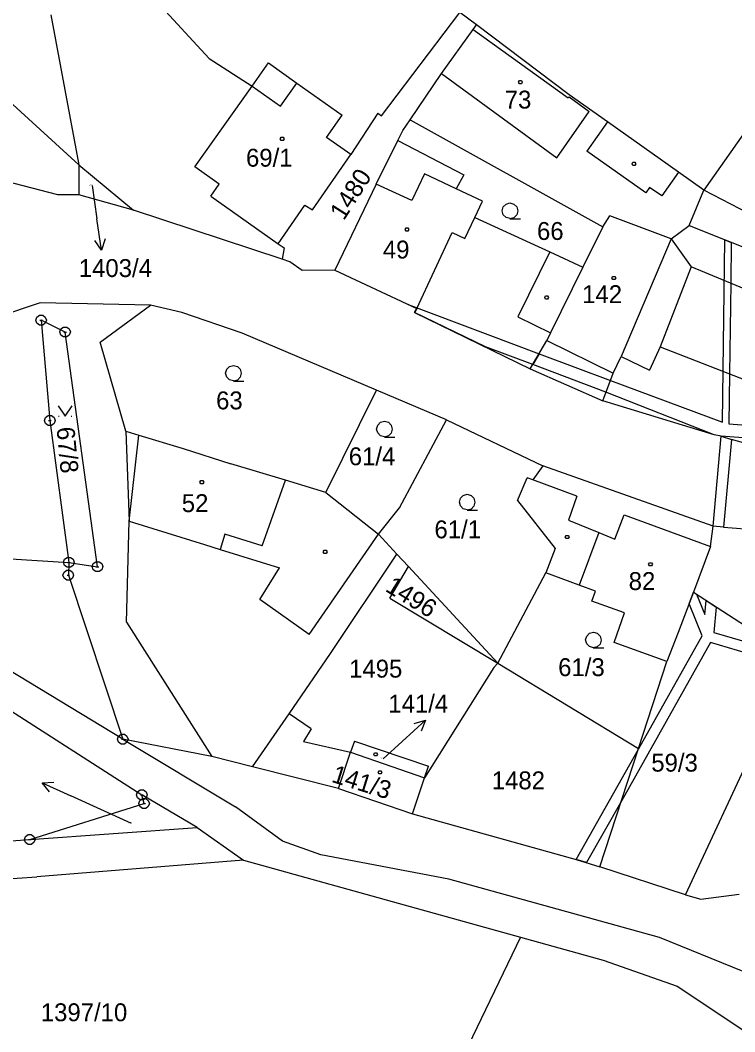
# Model space of a CAD drawing. Extents: x -850689 to -847910, y -1058374 to -1054747.
# Drawn here: x -849235.3 to -849167.4, y -1056250.1 to -1056154 of the extents above; entities that cross this region are included whole.
import ezdxf

# ---------------------------------------------------------------- set-up
doc = ezdxf.new("R2010")
doc.units = 0
for name, color, linetype in [('KN_BREMENA', 7, 'Continuous'), ('KN_HRANICE', 7, 'Continuous'), ('KN_KULTURY', 7, 'Continuous'), ('KN_MEZNIKY', 7, 'Continuous'), ('KN_PARCELY', 7, 'Continuous'), ('KN_SLUCKY', 7, 'Continuous'), ('KN_STAVEBNI', 7, 'Continuous')]:
    doc.layers.add(name, color=color, linetype=linetype)

# ---------------------------------------------------------------- blocks, each defined once
blk = doc.blocks.new('304')
blk.add_lwpolyline([(0, 0), (-0.38, 0.1), (-0.65, 0.37), (-0.75, 0.74), (-0.65, 1.11), (-0.38, 1.38), (-0.01, 1.48), (0.36, 1.38), (0.63, 1.11), (0.73, 0.73), (0.63, 0.35), (0.36, 0.08), (-0.02, -0.02), (0.98, -0.02)])
blk = doc.blocks.new('314')
for p, q in [((-0.95, 0), (-0.85, 0)), ((0.85, 0), (0.95, 0))]:
    blk.add_line(p, q)
blk.add_lwpolyline([(-1, 1.5), (0, 0), (1, 1.5)])
blk = doc.blocks.new('10292')
blk.add_line((0, 3), (0, 0))
blk.add_lwpolyline([(-0.5, 2), (0, 3), (0.5, 2)])
blk = doc.blocks.new('402')
blk.add_lwpolyline([(0.09, 0.15), (0.18, 0), (0.09, -0.15), (-0.09, -0.15), (-0.18, 0), (-0.09, 0.15), (0.09, 0.15)])
blk = doc.blocks.new('105')
blk.add_line((-0.12, 0), (0.12, 0))
blk.add_lwpolyline([(0.15, 0.48), (0.4, 0.3), (0.5, 0.01), (0.4, -0.28), (0.15, -0.46), (-0.16, -0.46), (-0.41, -0.28), (-0.51, 0.01), (-0.41, 0.3), (-0.16, 0.48), (0.15, 0.48)])

msp = doc.modelspace()

# ---------------------------------------------------------------- linework, layer by layer
at = {"layer": 'KN_BREMENA'}
for p, q in [((-849168.3, -1056174.91), (-849167.7, -1056175.15)), ((-849182.44, -1056233.76), (-849176.53, -1056223.29))]:
    msp.add_line(p, q, dxfattribs=at)
for points in [[(-849179.61, -1056189.36), (-849186.57, -1056186.75), (-849185.97, -1056185.74), (-849179.19, -1056188.26), (-849168.53, -1056192.22), (-849168.3, -1056174.91)], [(-849167.7, -1056175.15), (-849167.75, -1056179.02), (-849167.87, -1056187.62), (-849167.93, -1056192.39)], [(-849167.93, -1056192.39), (-849153, -1056193.52), (-849137.98, -1056194.65), (-849138.63, -1056195.81), (-849147.02, -1056195.18), (-849168.67, -1056193.56), (-849169.32, -1056193.41), (-849179.61, -1056189.36)], [(-849176.53, -1056223.29), (-849170.45, -1056212.52), (-849171.68, -1056209.54), (-849171.71, -1056209.46), (-849171.3, -1056208.37), (-849171, -1056208.57), (-849170.2, -1056210.49), (-849170.09, -1056209.16), (-849169.12, -1056209.78), (-849169.34, -1056212.19)], [(-849169.34, -1056212.19), (-849162.17, -1056214.28), (-849161.61, -1056214.65), (-849161.96, -1056215.41), (-849169.66, -1056213.16), (-849178.11, -1056228.14), (-849181.45, -1056234.05), (-849182.44, -1056233.76)]]:
    msp.add_lwpolyline(points, dxfattribs=at)
for points in [[(-849186.57, -1056186.75), (-849191.06, -1056185.07), (-849197.79, -1056181.8), (-849197.58, -1056181.42), (-849198.41, -1056181.03), (-849185.97, -1056185.74)], [(-849168.67, -1056193.56), (-849167.69, -1056193.85), (-849168.44, -1056202.2), (-849169.42, -1056202.11)]]:
    msp.add_lwpolyline(points, close=True, dxfattribs=at)
at = {"layer": 'KN_HRANICE'}
for p, q in [((-849253.4, -1056146.22), (-849229.69, -1056167.78)), ((-849222.61, -1056151.92), (-849217.32, -1056157.67)), ((-849232.38, -1056153.52), (-849229.69, -1056167.78)), ((-849200.94, -1056163.12), (-849193.48, -1056153.3)), ((-849191.92, -1056154.48), (-849193.48, -1056153.3)), ((-849192.23, -1056154.91), (-849191.92, -1056154.48)), ((-849183.09, -1056161.13), (-849191.92, -1056154.48)), ((-849195.24, -1056159.11), (-849192.23, -1056154.91)), ((-849217.32, -1056157.67), (-849213.24, -1056160.29)), ((-849213.24, -1056160.29), (-849211.69, -1056158.1)), ((-849211.69, -1056158.1), (-849209, -1056160.01)), ((-849198.23, -1056163.51), (-849195.24, -1056159.11)), ((-849218.67, -1056167.97), (-849213.24, -1056160.29)), ((-849209, -1056160.01), (-849204.67, -1056163.07)), ((-849179.47, -1056163.69), (-849183.09, -1056161.13)), ((-849163.93, -1056161.11), (-849170.31, -1056170.18)), ((-849206.17, -1056165.19), (-849204.67, -1056163.07)), ((-849201.3, -1056162.87), (-849203.87, -1056166.8)), ((-849201.3, -1056162.87), (-849200.94, -1056163.12)), ((-849198.91, -1056164.5), (-849198.23, -1056163.51)), ((-849198.23, -1056163.51), (-849179.92, -1056173.67)), ((-849172.72, -1056168.47), (-849179.47, -1056163.69)), ((-849199.39, -1056165.45), (-849198.91, -1056164.5)), ((-849203.87, -1056166.8), (-849206.17, -1056165.19)), ((-849201.46, -1056169.6), (-849199.39, -1056165.45)), ((-849199.39, -1056165.45), (-849193.13, -1056168.74)), ((-849207.51, -1056172.06), (-849203.87, -1056166.8)), ((-849229.69, -1056167.78), (-849229.7, -1056170.62)), ((-849229.69, -1056167.78), (-849224.5, -1056172.08)), ((-849216.36, -1056169.6), (-849218.67, -1056167.97)), ((-849231.7, -1056170.64), (-849240.7, -1056168.28)), ((-849193.13, -1056168.74), (-849193.84, -1056170.06)), ((-849170.31, -1056170.18), (-849172.72, -1056168.47)), ((-849217.17, -1056170.75), (-849216.36, -1056169.6)), ((-849201.46, -1056169.6), (-849205.39, -1056177.77)), ((-849229.7, -1056170.62), (-849231.7, -1056170.64)), ((-849224.5, -1056172.08), (-849229.7, -1056170.62)), ((-849217.17, -1056170.75), (-849210.75, -1056175.28)), ((-849191.35, -1056171.24), (-849193.84, -1056170.06)), ((-849171.71, -1056173.55), (-849170.31, -1056170.18)), ((-849157.98, -1056176.57), (-849170.31, -1056170.18)), ((-849210.75, -1056175.28), (-849208.24, -1056171.61)), ((-849208.24, -1056171.61), (-849207.51, -1056172.06)), ((-849192.07, -1056172.77), (-849191.35, -1056171.24)), ((-849210.39, -1056176.75), (-849224.5, -1056172.08)), ((-849192.07, -1056172.77), (-849184.95, -1056176.04)), ((-849179.92, -1056173.67), (-849179.25, -1056172.62)), ((-849173.41, -1056174.79), (-849179.25, -1056172.62)), ((-849179.92, -1056173.67), (-849181.8, -1056177.49)), ((-849173.41, -1056174.79), (-849171.71, -1056173.55)), ((-849171.71, -1056173.55), (-849158.94, -1056178.64)), ((-849210.75, -1056175.28), (-849210.2, -1056175.67)), ((-849210.2, -1056175.67), (-849210.39, -1056176.75)), ((-849173.41, -1056174.79), (-849171.52, -1056177.46)), ((-849184.95, -1056176.04), (-849181.8, -1056177.49)), ((-849209.65, -1056177), (-849210.39, -1056176.75)), ((-849208.48, -1056177.82), (-849209.65, -1056177)), ((-849181.8, -1056177.49), (-849184.87, -1056183.74)), ((-849171.52, -1056177.46), (-849174.47, -1056185.05)), ((-849205.39, -1056177.77), (-849208.48, -1056177.82)), ((-849205.39, -1056177.77), (-849197.58, -1056181.42)), ((-849233.39, -1056180.87), (-849242.54, -1056183.94)), ((-849222.9, -1056181.1), (-849233.39, -1056180.87)), ((-849227.69, -1056184.62), (-849222.9, -1056181.1)), ((-849219.9, -1056181.81), (-849222.9, -1056181.1)), ((-849197.58, -1056181.42), (-849197.79, -1056181.8)), ((-849214.19, -1056183.77), (-849219.9, -1056181.81)), ((-849197.79, -1056181.8), (-849186.8, -1056187.14)), ((-849231.01, -1056183.66), (-849233.29, -1056182.54)), ((-849233.29, -1056182.54), (-849232.46, -1056192.07)), ((-849227.93, -1056205.95), (-849231.01, -1056183.66)), ((-849201.43, -1056189.17), (-849214.19, -1056183.77)), ((-849184.87, -1056183.74), (-849185.22, -1056184.46)), ((-849225.23, -1056193.06), (-849227.69, -1056184.62)), ((-849186.8, -1056187.14), (-849185.22, -1056184.46)), ((-849174.47, -1056185.05), (-849175.47, -1056187.27)), ((-849178.93, -1056187.55), (-849178.15, -1056185.97)), ((-849178.15, -1056185.97), (-849175.47, -1056187.27)), ((-849186.8, -1056187.14), (-849179.92, -1056190.19)), ((-849179.92, -1056190.19), (-849178.93, -1056187.55)), ((-849206.24, -1056198.9), (-849201.43, -1056189.17)), ((-849194.76, -1056191.99), (-849201.43, -1056189.17)), ((-849169.32, -1056193.41), (-849179.92, -1056190.19)), ((-849199.24, -1056200.34), (-849194.76, -1056191.99)), ((-849194.76, -1056191.99), (-849185.6, -1056196.38)), ((-849232.46, -1056192.07), (-849230.65, -1056205.54)), ((-849225.23, -1056193.06), (-849224.93, -1056201.61)), ((-849225.23, -1056193.06), (-849223.99, -1056193.45)), ((-849223.99, -1056193.45), (-849219.79, -1056194.73)), ((-849168.67, -1056193.56), (-849169.32, -1056193.41)), ((-849168.67, -1056193.56), (-849167.69, -1056193.85)), ((-849164.4, -1056194.78), (-849167.69, -1056193.85)), ((-849219.79, -1056194.73), (-849215.25, -1056196.17)), ((-849210.06, -1056197.72), (-849215.25, -1056196.17)), ((-849185.6, -1056196.38), (-849186.57, -1056197.69)), ((-849169.42, -1056202.11), (-849185.6, -1056196.38)), ((-849206.24, -1056198.9), (-849210.06, -1056197.72)), ((-849188.02, -1056199.66), (-849187.1, -1056197.5)), ((-849186.57, -1056197.69), (-849187.1, -1056197.5)), ((-849206.24, -1056198.9), (-849201.22, -1056202.84)), ((-849188.02, -1056199.66), (-849184.45, -1056204.23)), ((-849201.22, -1056202.84), (-849199.24, -1056200.34)), ((-849225.19, -1056211.22), (-849224.93, -1056201.61)), ((-849225.53, -1056222.34), (-849258.09, -1056202.55)), ((-849169.66, -1056204.02), (-849169.42, -1056202.11)), ((-849168.44, -1056202.2), (-849169.42, -1056202.11)), ((-849168.44, -1056202.2), (-849162.53, -1056202.65)), ((-849201.22, -1056202.84), (-849199.47, -1056204.74)), ((-849184.45, -1056204.23), (-849185.31, -1056206.53)), ((-849169.66, -1056204.02), (-849171.3, -1056208.37)), ((-849259.01, -1056204.96), (-849223.72, -1056227.62)), ((-849236.17, -1056205.21), (-849230.65, -1056205.54)), ((-849205.78, -1056214.2), (-849199.47, -1056204.74)), ((-849199.47, -1056204.74), (-849198.37, -1056205.93)), ((-849230.65, -1056205.54), (-849230.7, -1056206.76)), ((-849230.65, -1056205.54), (-849227.93, -1056205.95)), ((-849200.16, -1056208.92), (-849198.37, -1056205.93)), ((-849198.37, -1056205.93), (-849189.89, -1056215.12)), ((-849230.7, -1056206.76), (-849225.53, -1056222.34)), ((-849189.89, -1056215.12), (-849185.31, -1056206.53)), ((-849182.16, -1056207.7), (-849185.31, -1056206.53)), ((-849180.61, -1056208.28), (-849182.16, -1056207.7)), ((-849180.96, -1056209.23), (-849180.61, -1056208.28)), ((-849171.3, -1056208.37), (-849172.75, -1056212.2)), ((-849171.3, -1056208.37), (-849161.61, -1056214.65)), ((-849200.16, -1056208.92), (-849189.89, -1056215.12)), ((-849177.84, -1056210.33), (-849180.96, -1056209.23)), ((-849225.19, -1056211.22), (-849217.08, -1056223.98)), ((-849178.84, -1056213.13), (-849177.84, -1056210.33)), ((-849172.75, -1056212.2), (-849173.81, -1056214.95)), ((-849173.81, -1056214.95), (-849178.84, -1056213.13)), ((-849209.73, -1056219.93), (-849205.78, -1056214.2)), ((-849189.89, -1056215.12), (-849190.25, -1056215.51)), ((-849189.89, -1056215.12), (-849176.5, -1056223.2)), ((-849176.5, -1056223.2), (-849173.81, -1056214.95)), ((-849172.06, -1056237.11), (-849161.61, -1056214.65)), ((-849190.25, -1056215.51), (-849196.84, -1056226)), ((-849213.19, -1056224.95), (-849209.73, -1056219.93)), ((-849207.63, -1056221.36), (-849209.73, -1056219.93)), ((-849207.63, -1056221.36), (-849208.34, -1056222.56)), ((-849217.08, -1056223.98), (-849225.53, -1056222.34)), ((-849225.53, -1056222.34), (-849214.82, -1056228.77)), ((-849208.34, -1056222.56), (-849203.88, -1056223.57)), ((-849203.52, -1056222.51), (-849203.88, -1056223.57)), ((-849203.52, -1056222.51), (-849196.47, -1056224.89)), ((-849203.88, -1056223.57), (-849196.84, -1056226)), ((-849180.18, -1056234.46), (-849176.5, -1056223.2)), ((-849213.19, -1056224.95), (-849217.08, -1056223.98)), ((-849205.03, -1056227), (-849213.19, -1056224.95)), ((-849196.84, -1056226), (-849196.47, -1056224.89)), ((-849197.99, -1056229.41), (-849196.84, -1056226)), ((-849205.03, -1056227), (-849197.99, -1056229.41)), ((-849234.37, -1056231.86), (-849223.5, -1056228.45)), ((-849218.47, -1056230.72), (-849223.72, -1056227.62)), ((-849223.5, -1056228.45), (-849223.72, -1056227.62)), ((-849210.34, -1056232), (-849214.82, -1056228.77)), ((-849197.99, -1056229.41), (-849182.44, -1056233.76)), ((-849234.37, -1056231.86), (-849218.47, -1056230.72)), ((-849218.47, -1056230.72), (-849214.07, -1056233.83)), ((-849244.07, -1056232.54), (-849234.37, -1056231.86)), ((-849206.7, -1056233.3), (-849210.34, -1056232)), ((-849194.53, -1056235.61), (-849206.7, -1056233.3)), ((-849214.07, -1056233.83), (-849233.7, -1056235.39)), ((-849214.07, -1056233.83), (-849187.73, -1056241.12)), ((-849182.44, -1056233.76), (-849180.18, -1056234.46)), ((-849172.06, -1056237.11), (-849180.18, -1056234.46)), ((-849273.28, -1056238.25), (-849233.7, -1056235.39)), ((-849174.51, -1056241.18), (-849194.53, -1056235.61)), ((-849172.06, -1056237.11), (-849170.59, -1056237.53)), ((-849170.59, -1056237.53), (-849166.94, -1056237.05)), ((-849187.73, -1056241.12), (-849195.81, -1056257.87)), ((-849187.73, -1056241.12), (-849179.87, -1056243.33)), ((-849166.56, -1056244.39), (-849174.51, -1056241.18)), ((-849179.87, -1056243.33), (-849172.85, -1056245.8)), ((-849172.85, -1056245.8), (-849164.8, -1056251.16))]:
    msp.add_line(p, q, dxfattribs=at)
at = {"layer": 'KN_PARCELY'}
for p, q in [((-849228.45, -1056169.74), (-849227.99, -1056172.91)), ((-849200.78, -1056224.19), (-849198.99, -1056222.55)), ((-849224.75, -1056230.31), (-849230.46, -1056227.71))]:
    msp.add_line(p, q, dxfattribs=at)
at = {"layer": 'KN_SLUCKY'}
for p, q in [((-849192.23, -1056154.91), (-849183.2, -1056161.41)), ((-849195.24, -1056159.11), (-849184.29, -1056167.12)), ((-849213.24, -1056160.29), (-849210.54, -1056162.19)), ((-849210.54, -1056162.19), (-849209, -1056160.01)), ((-849183.2, -1056161.41), (-849183.11, -1056161.33)), ((-849183.11, -1056161.33), (-849181.19, -1056162.7)), ((-849184.29, -1056167.12), (-849181.19, -1056162.7)), ((-849179.47, -1056163.69), (-849181.44, -1056166.48)), ((-849175.83, -1056170.45), (-849181.44, -1056166.48)), ((-849196.86, -1056168.63), (-849198.06, -1056171.16)), ((-849193.84, -1056170.06), (-849196.86, -1056168.63)), ((-849172.72, -1056168.47), (-849174.31, -1056170.73)), ((-849198.06, -1056171.16), (-849201.46, -1056169.6)), ((-849175.46, -1056169.92), (-849175.83, -1056170.45)), ((-849174.31, -1056170.73), (-849175.46, -1056169.92)), ((-849193.01, -1056174.76), (-849192.07, -1056172.77)), ((-849197.58, -1056181.42), (-849194.23, -1056174.19)), ((-849194.23, -1056174.19), (-849193.01, -1056174.76)), ((-849173.41, -1056174.79), (-849178.15, -1056185.97)), ((-849184.95, -1056176.04), (-849187.98, -1056182.21)), ((-849151.28, -1056185.84), (-849171.52, -1056177.46)), ((-849187.98, -1056182.21), (-849184.87, -1056183.74)), ((-849185.22, -1056184.46), (-849178.93, -1056187.55)), ((-849174.47, -1056185.05), (-849160.38, -1056190.53)), ((-849224.93, -1056201.61), (-849223.99, -1056193.45)), ((-849212.29, -1056203.97), (-849210.06, -1056197.72)), ((-849182.36, -1056199.24), (-849186.57, -1056197.69)), ((-849182.36, -1056199.24), (-849183.16, -1056201.52)), ((-849224.93, -1056201.61), (-849217.77, -1056203.84)), ((-849183.16, -1056201.52), (-849180.29, -1056202.7)), ((-849178.76, -1056203.33), (-849177.88, -1056201.01)), ((-849177.88, -1056201.01), (-849169.66, -1056204.02)), ((-849215.83, -1056202.87), (-849216.27, -1056204.31)), ((-849212.29, -1056203.97), (-849215.83, -1056202.87)), ((-849207.8, -1056212.38), (-849201.22, -1056202.84)), ((-849180.29, -1056202.7), (-849182.16, -1056207.7)), ((-849180.29, -1056202.7), (-849178.76, -1056203.33)), ((-849217.77, -1056203.84), (-849216.27, -1056204.31)), ((-849216.27, -1056204.31), (-849210.64, -1056206.06)), ((-849212.49, -1056209.07), (-849210.64, -1056206.06)), ((-849207.8, -1056212.38), (-849212.49, -1056209.07)), ((-849205.03, -1056227), (-849203.88, -1056223.57))]:
    msp.add_line(p, q, dxfattribs=at)
at = {"layer": 'KN_STAVEBNI'}
for p, q in [((-849195.24, -1056159.11), (-849192.23, -1056154.91)), ((-849192.23, -1056154.91), (-849183.2, -1056161.41)), ((-849195.24, -1056159.11), (-849184.29, -1056167.12)), ((-849218.67, -1056167.97), (-849213.24, -1056160.29)), ((-849213.24, -1056160.29), (-849210.54, -1056162.19)), ((-849210.54, -1056162.19), (-849209, -1056160.01)), ((-849209, -1056160.01), (-849204.67, -1056163.07)), ((-849183.2, -1056161.41), (-849183.11, -1056161.33)), ((-849183.11, -1056161.33), (-849181.19, -1056162.7)), ((-849206.17, -1056165.19), (-849204.67, -1056163.07)), ((-849184.29, -1056167.12), (-849181.19, -1056162.7)), ((-849203.87, -1056166.8), (-849206.17, -1056165.19)), ((-849207.51, -1056172.06), (-849203.87, -1056166.8)), ((-849216.36, -1056169.6), (-849218.67, -1056167.97)), ((-849196.86, -1056168.63), (-849198.06, -1056171.16)), ((-849193.84, -1056170.06), (-849196.86, -1056168.63)), ((-849217.17, -1056170.75), (-849216.36, -1056169.6)), ((-849201.46, -1056169.6), (-849205.39, -1056177.77)), ((-849198.06, -1056171.16), (-849201.46, -1056169.6)), ((-849217.17, -1056170.75), (-849210.75, -1056175.28)), ((-849191.35, -1056171.24), (-849193.84, -1056170.06)), ((-849210.75, -1056175.28), (-849208.24, -1056171.61)), ((-849208.24, -1056171.61), (-849207.51, -1056172.06)), ((-849192.07, -1056172.77), (-849191.35, -1056171.24)), ((-849193.01, -1056174.76), (-849192.07, -1056172.77)), ((-849179.92, -1056173.67), (-849179.25, -1056172.62)), ((-849173.41, -1056174.79), (-849179.25, -1056172.62)), ((-849179.92, -1056173.67), (-849181.8, -1056177.49)), ((-849197.58, -1056181.42), (-849194.23, -1056174.19)), ((-849194.23, -1056174.19), (-849193.01, -1056174.76)), ((-849173.41, -1056174.79), (-849178.15, -1056185.97)), ((-849181.8, -1056177.49), (-849184.87, -1056183.74)), ((-849171.52, -1056177.46), (-849174.47, -1056185.05)), ((-849151.28, -1056185.84), (-849171.52, -1056177.46)), ((-849205.39, -1056177.77), (-849197.58, -1056181.42)), ((-849184.87, -1056183.74), (-849185.22, -1056184.46)), ((-849185.22, -1056184.46), (-849178.93, -1056187.55)), ((-849174.47, -1056185.05), (-849160.38, -1056190.53)), ((-849178.93, -1056187.55), (-849178.15, -1056185.97)), ((-849224.93, -1056201.61), (-849223.99, -1056193.45)), ((-849223.99, -1056193.45), (-849219.79, -1056194.73)), ((-849219.79, -1056194.73), (-849215.25, -1056196.17)), ((-849210.06, -1056197.72), (-849215.25, -1056196.17)), ((-849212.29, -1056203.97), (-849210.06, -1056197.72)), ((-849224.93, -1056201.61), (-849217.77, -1056203.84)), ((-849178.76, -1056203.33), (-849177.88, -1056201.01)), ((-849177.88, -1056201.01), (-849169.66, -1056204.02)), ((-849215.83, -1056202.87), (-849216.27, -1056204.31)), ((-849212.29, -1056203.97), (-849215.83, -1056202.87)), ((-849180.29, -1056202.7), (-849182.16, -1056207.7)), ((-849180.29, -1056202.7), (-849178.76, -1056203.33)), ((-849217.77, -1056203.84), (-849216.27, -1056204.31)), ((-849169.66, -1056204.02), (-849171.3, -1056208.37)), ((-849180.61, -1056208.28), (-849182.16, -1056207.7)), ((-849180.96, -1056209.23), (-849180.61, -1056208.28)), ((-849171.3, -1056208.37), (-849172.75, -1056212.2)), ((-849177.84, -1056210.33), (-849180.96, -1056209.23)), ((-849178.84, -1056213.13), (-849177.84, -1056210.33)), ((-849172.75, -1056212.2), (-849173.81, -1056214.95)), ((-849173.81, -1056214.95), (-849178.84, -1056213.13)), ((-849203.52, -1056222.51), (-849203.88, -1056223.57)), ((-849203.52, -1056222.51), (-849196.47, -1056224.89)), ((-849205.03, -1056227), (-849203.88, -1056223.57)), ((-849196.84, -1056226), (-849196.47, -1056224.89)), ((-849197.99, -1056229.41), (-849196.84, -1056226)), ((-849205.03, -1056227), (-849197.99, -1056229.41))]:
    msp.add_line(p, q, dxfattribs=at)

# ---------------------------------------------------------------- block references
at = {"layer": 'KN_KULTURY'}
for name, p in [('402', (-849187.74, -1056159.93)), ('402', (-849210.38, -1056165.31)), ('402', (-849176.95, -1056167.68)), ('304', (-849188.72, -1056172.88)), ('402', (-849198.52, -1056173.91)), ('402', (-849178.86, -1056178.52)), ('402', (-849185.25, -1056180.37)), ('304', (-849215, -1056188.3)), ('304', (-849200.65, -1056193.61)), ('402', (-849218.01, -1056197.91)), ('304', (-849192.79, -1056200.55)), ('402', (-849183.29, -1056203.12)), ('402', (-849206.29, -1056204.53)), ('402', (-849175.38, -1056205.72)), ('304', (-849180.79, -1056213.64)), ('402', (-849201.5, -1056223.77)), ('402', (-849201.08, -1056225.48))]:
    msp.add_blockref(name, p, dxfattribs=at)
at = {"layer": 'KN_KULTURY', "xscale": 0.67, "yscale": 0.67}
msp.add_blockref('314', (-849231, -1056191.66), dxfattribs=at)
at = {"layer": 'KN_MEZNIKY'}
for p in [(-849233.29, -1056182.54), (-849231.01, -1056183.66), (-849232.46, -1056192.07), (-849230.65, -1056205.54), (-849227.93, -1056205.95), (-849230.7, -1056206.76), (-849225.53, -1056222.34), (-849223.72, -1056227.62), (-849223.5, -1056228.45), (-849234.37, -1056231.86)]:
    msp.add_blockref('105', p, dxfattribs=at)
at = {"layer": 'KN_PARCELY'}
for p, rotation in [((-849227.99, -1056172.91), -171.726069), ((-849198.99, -1056222.55), -47.62341000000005), ((-849230.46, -1056227.71), 65.489076)]:
    msp.add_blockref('10292', p, dxfattribs=dict(at, rotation=rotation))

# ---------------------------------------------------------------- texts
for s, height, p in [('73', 1.7, (-849189.229, -1056162.43)), ('69/1', 1.7, (-849213.817, -1056167.95)), ('1403/4', 0.1, (-849228.75, -1056169.74)), ('66', 1.7, (-849186.16, -1056174.91)), ('49', 1.7, (-849200.809, -1056176.67)), ('1403/4', 1.7, (-849229.71, -1056178.43)), ('142', 1.7, (-849181.87, -1056180.91)), ('63', 1.7, (-849216.66, -1056191)), ('61/4', 1.7, (-849204.05, -1056196.31)), ('52', 1.7, (-849219.919, -1056200.76)), ('61/1', 1.7, (-849195.907, -1056203.25)), ('82', 1.7, (-849177.449, -1056208.16)), ('1495', 1.7, (-849204.02, -1056216.48)), ('61/3', 1.7, (-849184.15, -1056216.34)), ('141/4', 1.7, (-849200.29, -1056219.8)), ('59/3', 1.7, (-849175.299, -1056225.41)), ('141/4', 0.1, (-849201.032, -1056224.19)), ('1482', 1.7, (-849190.46, -1056227.09)), ('67/11', 0.1, (-849224.981, -1056230.31)), ('1397/10', 1.7, (-849233.319, -1056249.12))]:
    msp.add_text(s, height=height, dxfattribs=at).set_placement(p)
for s, rotation, p in [('1480', 57.582, (-849204.521, -1056173.136)), ('67/8', 275.421, (-849231.827, -1056192.736)), ('1496', 328.305, (-849200.678, -1056208.205)), ('141/3', 342.743, (-849205.779, -1056226.369))]:
    msp.add_text(s, height=1.7, rotation=rotation, dxfattribs=at).set_placement(p)

doc.saveas('drawing.dxf')
